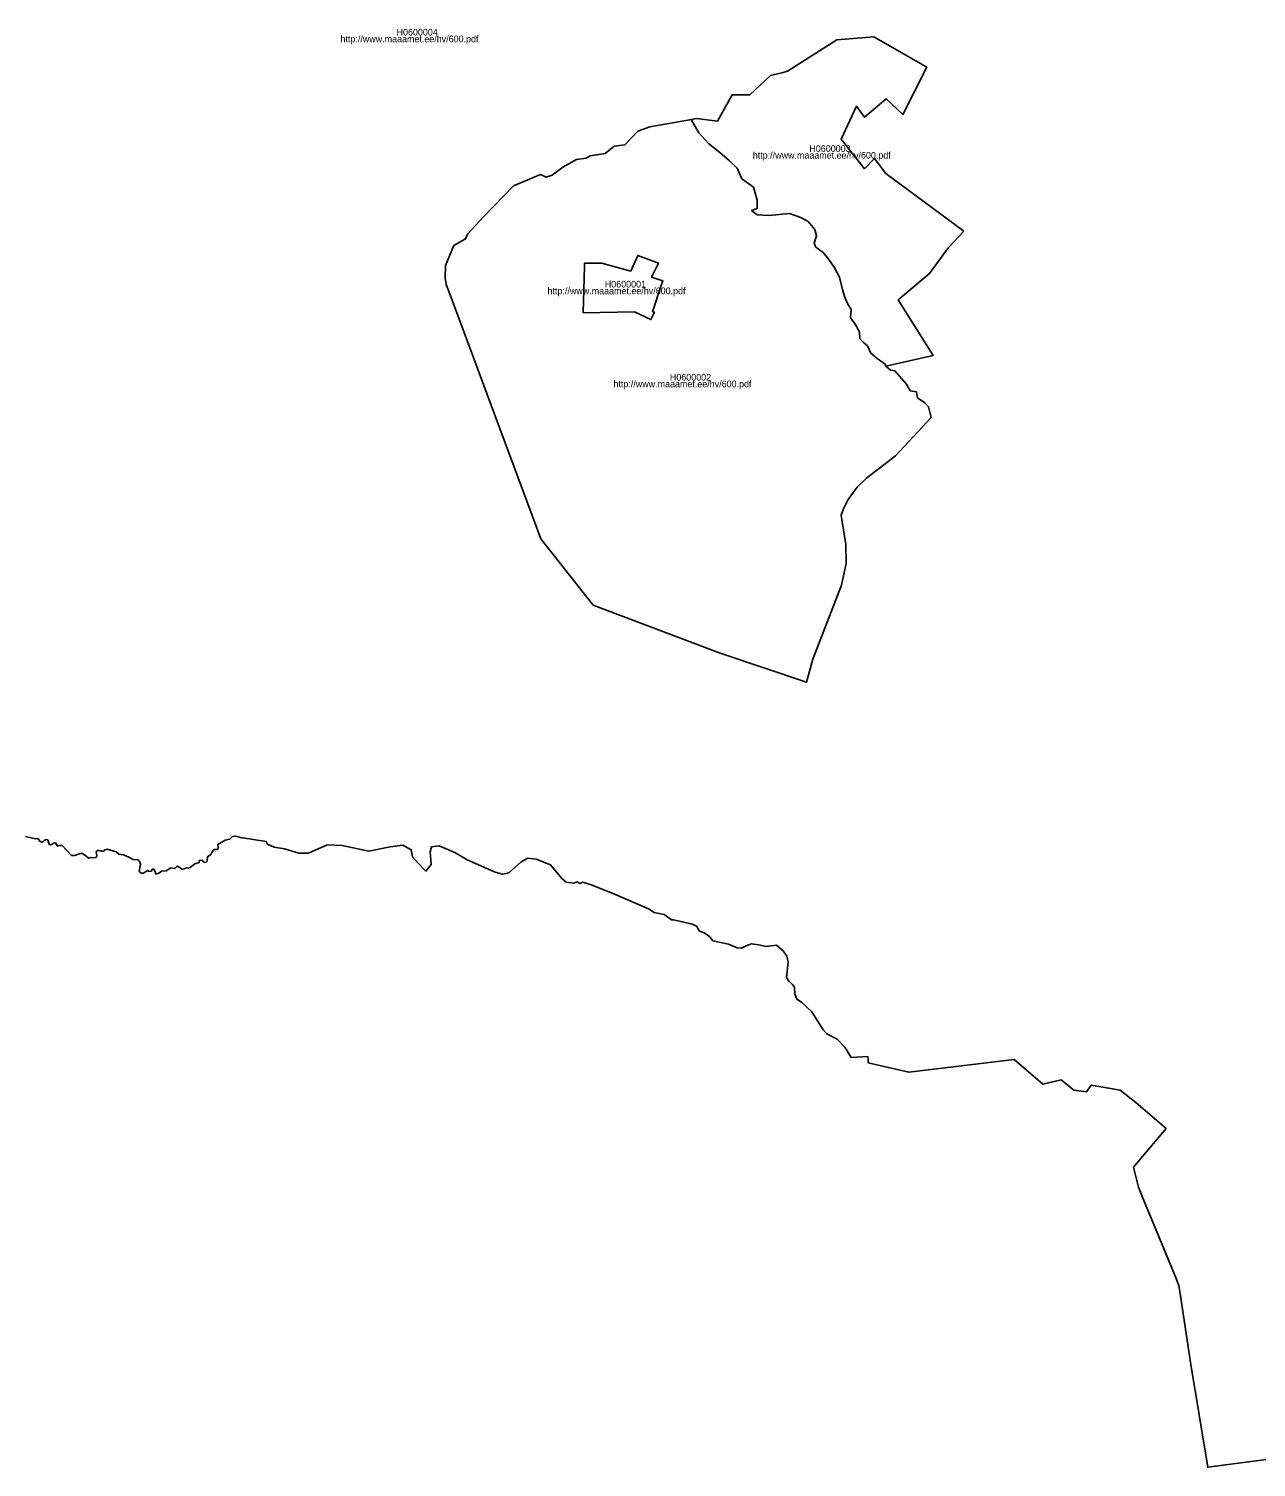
# Model space of a CAD drawing. Extents: x 369010 to 739155, y 6377141 to 6634081.
# Drawn here: x 588944 to 593540, y 6437007 to 6442393 of the extents above; entities that cross this region are included whole.
import ezdxf

# ---------------------------------------------------------------- set-up
doc = ezdxf.new("R2010")
doc.units = 0
for name, color, linetype in [('H_LINK', 7, 'Continuous'), ('H_PIIR', 7, 'Continuous'), ('H_TUNNUS', 7, 'Continuous')]:
    doc.layers.add(name, color=color, linetype=linetype)

msp = doc.modelspace()

# ---------------------------------------------------------------- linework, layer by layer
at = {"layer": 'H_PIIR'}
for points in [[(592108.2801, 6442363), (591969.52, 6442351.0799), (591785.26, 6442234.28), (591768.3599, 6442229.9701), (591721.22, 6442217.95), (591643.37, 6442146.3701), (591577.4501, 6442145.7401), (591522.83, 6442047.16), (591444.0299, 6442056.58), (591424.6895, 6442053.1702), (591269.5, 6442025.81), (591224.9201, 6442010.1099), (591175.3201, 6441958.62), (591135.4601, 6441953.6001), (591102.18, 6441926.6), (591046.3, 6441917.1799), (591031.24, 6441909.0199), (590994.2001, 6441903.3599), (590943.9701, 6441875.1101), (590903.79, 6441844.97), (590881.0701, 6441837.78), (590860.1499, 6441847.4801), (590788.6099, 6441817.26), (590759.07, 6441804.7801), (590647.3199, 6441689.8699), (590586.1099, 6441624.5699), (590579.1999, 6441606.36), (590535.25, 6441581.8699), (590504.49, 6441506.5201), (590503.23, 6441459.42), (590506.9999, 6441435.56), (590521.5299, 6441396.53), (590861.72, 6440483), (591057.6101, 6440234.97), (591533.18, 6440055.3801), (591855.5701, 6439946.1299), (591879.43, 6440033.4101), (591987.1001, 6440309.6899), (592004.06, 6440391.32), (592003.43, 6440462.28), (591985.54, 6440572.1599), (591993.7, 6440592.89), (592003.1099, 6440612.98), (592011.9001, 6440631.1901), (592045.8099, 6440676.4), (592080.34, 6440710.94), (592189.5799, 6440793.8199), (592322.9901, 6440938.24), (592312.9499, 6440977.7999), (592299.1399, 6440992.8699), (592271.5099, 6441011.71), (592267.12, 6441034.3199), (592244.5101, 6441038.08), (592230.0701, 6441062.57), (592186.7501, 6441112.8099), (592169.8, 6441114.6901), (592153.1599, 6441130.39), (592329.58, 6441169.9499), (592199.62, 6441377.7901), (592316.71, 6441477.0001), (592387.0301, 6441574.33), (592444.79, 6441635.24), (592153.1599, 6441850.61), (592110.4699, 6441907.13), (592073.43, 6441868.8201), (591986.16, 6441979.34), (592042.67, 6442103.6701), (592072.4901, 6442062.22), (592154.11, 6442131.2901), (592216.89, 6442072.27), (592306.0399, 6442248.72)], [(592108.2801, 6442363), (592306.0399, 6442248.72), (592216.89, 6442072.27), (592154.11, 6442131.2901), (592072.4901, 6442062.22), (592042.67, 6442103.6701), (591986.16, 6441979.34), (592073.43, 6441868.8201), (592110.4699, 6441907.13), (592153.1599, 6441850.61), (592444.79, 6441635.24), (592387.0301, 6441574.33), (592316.71, 6441477.0001), (592199.62, 6441377.7901), (592329.58, 6441169.9499), (592153.1599, 6441130.39), (592150.05, 6441137.56), (592120.08, 6441159.1001), (592097.03, 6441179.09), (592083.9599, 6441205.7899), (592068.59, 6441219.6299), (592055.53, 6441232.7), (592053.9899, 6441258.08), (592038.62, 6441286.5299), (592020.95, 6441311), (592022.49, 6441342.5199), (592009.42, 6441364.82), (591998.6701, 6441390.9699), (591990.98, 6441417.11), (591979.45, 6441462.4799), (591959.4701, 6441500.5199), (591939.5, 6441528.9501), (591918.75, 6441555.08), (591891.08, 6441575.83), (591884.17, 6441590.43), (591893.39, 6441618.09), (591886.47, 6441641.15), (591861.8801, 6441671.12), (591834.2201, 6441686.5001), (591792.7201, 6441702.0601), (591714.92, 6441694.28), (591670.8299, 6441696.8701), (591650.0799, 6441712.4301), (591670.8299, 6441720.22), (591670.8299, 6441751.34), (591657.86, 6441800.6099), (591613.7701, 6441831.7399), (591595.62, 6441870.64), (591567.0901, 6441899.17), (591530.7801, 6441930.29), (591489.28, 6441964.0101), (591452.97, 6442002.91), (591425.7701, 6442051.25), (591424.6895, 6442053.1702), (591444.0299, 6442056.58), (591522.83, 6442047.16), (591577.4501, 6442145.7401), (591643.37, 6442146.3701), (591721.22, 6442217.95), (591768.3599, 6442229.9701), (591785.26, 6442234.28), (591969.52, 6442351.0799)], [(591424.6895, 6442053.1702), (591425.7701, 6442051.25), (591452.97, 6442002.91), (591489.28, 6441964.0101), (591530.7801, 6441930.29), (591567.0901, 6441899.17), (591595.62, 6441870.64), (591613.7701, 6441831.7399), (591657.86, 6441800.6099), (591670.8299, 6441751.34), (591670.8299, 6441720.22), (591650.0799, 6441712.4301), (591670.8299, 6441696.8701), (591714.92, 6441694.28), (591792.7201, 6441702.0601), (591834.2201, 6441686.5001), (591861.8801, 6441671.12), (591886.47, 6441641.15), (591893.39, 6441618.09), (591884.17, 6441590.43), (591891.08, 6441575.83), (591918.75, 6441555.08), (591939.5, 6441528.9501), (591959.4701, 6441500.5199), (591979.45, 6441462.4799), (591990.98, 6441417.11), (591998.6701, 6441390.9699), (592009.42, 6441364.82), (592022.49, 6441342.5199), (592020.95, 6441311), (592038.62, 6441286.5299), (592053.9899, 6441258.08), (592055.53, 6441232.7), (592068.59, 6441219.6299), (592083.9599, 6441205.7899), (592097.03, 6441179.09), (592120.08, 6441159.1001), (592150.05, 6441137.56), (592153.1599, 6441130.39), (592155.1686, 6441128.4949), (592169.8, 6441114.6901), (592186.7501, 6441112.8099), (592230.0701, 6441062.57), (592244.5101, 6441038.08), (592267.12, 6441034.3199), (592271.5099, 6441011.71), (592299.1399, 6440992.8699), (592312.9499, 6440977.7999), (592322.9901, 6440938.24), (592189.5799, 6440793.8199), (592080.34, 6440710.94), (592045.8099, 6440676.4), (592011.9001, 6440631.1901), (592003.1099, 6440612.98), (591993.7, 6440592.89), (591985.54, 6440572.1599), (592003.43, 6440462.28), (592004.06, 6440391.32), (591987.1001, 6440309.6899), (591879.43, 6440033.4101), (591855.5701, 6439946.1299), (591533.18, 6440055.3801), (591057.6101, 6440234.97), (590861.72, 6440483), (590521.5299, 6441396.53), (590506.9999, 6441435.56), (590503.23, 6441459.42), (590504.49, 6441506.5201), (590535.25, 6441581.8699), (590579.1999, 6441606.36), (590586.1099, 6441624.5699), (590647.3199, 6441689.8699), (590759.07, 6441804.7801), (590788.6099, 6441817.26), (590860.1499, 6441847.4801), (590881.0701, 6441837.78), (590903.79, 6441844.97), (590943.9701, 6441875.1101), (590994.2001, 6441903.3599), (591031.24, 6441909.0199), (591046.3, 6441917.1799), (591102.18, 6441926.6), (591135.4601, 6441953.6001), (591175.3201, 6441958.62), (591224.9201, 6442010.1099), (591269.5, 6442025.81)], [(591224.03, 6441544.5701), (591301.84, 6441515.1701), (591275.9, 6441463.29), (591317.41, 6441449.45), (591312.22, 6441432.16), (591279.36, 6441333.59), (591286.28, 6441331.86), (591272.45, 6441304.19), (591211.92, 6441333.59), (591019.9699, 6441330.13), (591025.1599, 6441503.0601), (591025.1599, 6441515.1701), (591089.14, 6441515.1701), (591198.09, 6441485.77)], [(591089.14, 6441515.1701), (591025.1599, 6441515.1701), (591025.1599, 6441503.0601), (591019.9699, 6441330.13), (591211.92, 6441333.59), (591272.45, 6441304.19), (591286.28, 6441331.86), (591279.36, 6441333.59), (591312.22, 6441432.16), (591317.41, 6441449.45), (591275.9, 6441463.29), (591301.84, 6441515.1701), (591224.03, 6441544.5701), (591198.09, 6441485.77)]]:
    msp.add_lwpolyline(points, close=True, dxfattribs=at)
for points in [[(588931.56, 6439368.48), (588968.69, 6439360.0501), (588976.72, 6439361.06), (588981.5901, 6439357.51), (588984.89, 6439351), (588991.3901, 6439347.3399), (588995.25, 6439347.8499), (589001.2401, 6439353.54), (589009.06, 6439357.3), (589015.1601, 6439355.9799), (589019.7301, 6439340.13), (589024.46, 6439337.4199), (589032.2799, 6439340.67), (589037.5601, 6439345.6501), (589043.45, 6439344.63), (589051.3299, 6439332.74), (589057.6299, 6439334.6701), (589068.7601, 6439334.6701), (589104.3599, 6439298.3001), (589116.34, 6439297.7901), (589135.84, 6439304.8), (589145.14, 6439305.01), (589157.5299, 6439296.0601), (589167.4801, 6439287.4301), (589174.59, 6439290.37), (589186.3199, 6439288.9499), (589195.97, 6439290.2701), (589198.6101, 6439296.17), (589196.58, 6439312.2201), (589203.6799, 6439317.51), (589214.86, 6439313.44), (589224.77, 6439314.05), (589228.82, 6439319.34), (589237.96, 6439321.3699), (589271.48, 6439311.41), (589281.6901, 6439302.18), (589298.21, 6439299.84), (589318.83, 6439291.63), (589334.88, 6439282.48), (589352.35, 6439281.4899), (589358.8, 6439276.22), (589362.54, 6439265.72), (589356.7101, 6439239.65), (589363.74, 6439231.3399), (589373.3601, 6439231.2), (589388.65, 6439242.04), (589395.1799, 6439238.3801), (589403.3499, 6439239.24), (589406.2801, 6439246.56), (589411.83, 6439246.51), (589416.39, 6439240.32), (589419.5401, 6439228.4499), (589430.28, 6439231.52), (589440.7399, 6439238.9501), (589457.83, 6439240.1201), (589476.33, 6439251.0101), (589488.2701, 6439249.65), (589492.8801, 6439251.5099), (589497.8, 6439256.47), (589501.23, 6439257.47), (589509.25, 6439253.04), (589517.41, 6439246.3099), (589525.9, 6439248.34), (589536.27, 6439252.1399), (589542.06, 6439250.9199), (589548.6, 6439252.45), (589565.21, 6439266.16), (589581.6199, 6439271.45), (589582.38, 6439279.07), (589593.6499, 6439280.29), (589599.9, 6439272.8199), (589606.9, 6439271.7499), (589612.39, 6439276.4801), (589613.4501, 6439293.0899), (589625.15, 6439300.98), (589630.33, 6439311.95), (589637.6401, 6439320.03), (589650.08, 6439320.03), (589652.5199, 6439325.3599), (589652.21, 6439339.54), (589679.46, 6439355.5401), (589696.21, 6439359.3499), (589706.11, 6439368.6499), (589718.75, 6439369.72), (589736.04, 6439365.6), (589833.2801, 6439350.05), (589837.6999, 6439340), (589862.49, 6439328.56), (589900.8101, 6439322.16), (589954.4201, 6439306.3099), (589990.87, 6439306.4701), (590060.6101, 6439337.73), (590117.49, 6439334.6501), (590216.64, 6439313.8801), (590297.35, 6439330.8), (590344.23, 6439336.19), (590375.75, 6439319.27), (590381.13, 6439292.35), (590398.81, 6439271.58), (590431.09, 6439239.28), (590450.3, 6439263.89), (590446.7, 6439311.42), (590452.17, 6439330.79), (590481.0499, 6439334.21), (590538.8399, 6439309.14), (590585.3, 6439281.1101), (590690.0301, 6439235.21), (590718.1899, 6439227.46), (590741.65, 6439232.4699), (590786.8799, 6439274.1701), (590812.3901, 6439287.62), (590843.81, 6439284.2), (590897.9, 6439262.4899), (590940.26, 6439211.93), (590956.2, 6439197.3601), (590983.45, 6439194.24), (590997.79, 6439199.36), (591007.01, 6439192.53), (591018.62, 6439197.3099), (591049.9599, 6439188.43), (591134.9901, 6439153.91), (591264.0299, 6439098.26), (591285.21, 6439083.92), (591323.12, 6439076.51), (591350.5599, 6439056.5199), (591358.2401, 6439057.0399), (591428.41, 6439041.15), (591444.29, 6439033.4599), (591455.0499, 6439013.98), (591472.9799, 6439008.35), (591492.95, 6438993.99), (591505.2399, 6438978.1001), (591564.1501, 6438965.2899), (591596.08, 6438951.4499), (591611.9599, 6438950.4301), (591629.8899, 6438959.6501), (591650.37, 6438966.83), (591677.01, 6438963.24), (591703.64, 6438957.09), (591743.0801, 6438962.22), (591768.18, 6438941.2001), (591782.52, 6438921.21), (591787.64, 6438897.9401), (591781.5, 6438840.53), (591789.6899, 6438827.21), (591804.04, 6438814.39), (591811.2101, 6438804.65), (591812.7399, 6438780.0499), (591819.6899, 6438759.75), (591837.1001, 6438748.9899), (591875.52, 6438712.0799), (591918.03, 6438644.4599), (591931.86, 6438630.1199), (591970.79, 6438609.63), (591998.96, 6438579.9199), (592023.03, 6438542.01), (592084.88, 6438545.54), (592086.3901, 6438535.5301), (592086.45, 6438521.8001), (592238.5999, 6438486.23), (592633.09, 6438533.7899), (592741.2101, 6438441.13), (592809.1799, 6438457.26), (592856.41, 6438419.24), (592904.79, 6438413.48), (592922.07, 6438437.67), (593030.3601, 6438419.24), (593089.1101, 6438373.16), (593202.2001, 6438275.45), (593080.11, 6438131.37), (593098.54, 6438056.46), (593121.58, 6437999.9799), (593163.0401, 6437901.4199), (593240.2099, 6437713.55), (593249.4299, 6437687.04), (593254.0299, 6437665.24), (593294.35, 6437392.26), (593357.9901, 6437007.37), (593596.43, 6437038.46)], [(593596.43, 6437038.46), (593357.9901, 6437007.37), (593294.35, 6437392.26), (593254.0299, 6437665.24), (593249.4299, 6437687.04), (593240.2099, 6437713.55), (593163.0401, 6437901.4199), (593121.58, 6437999.9799), (593098.54, 6438056.46), (593080.11, 6438131.37), (593202.2001, 6438275.45), (593089.1101, 6438373.16), (593030.3601, 6438419.24), (592922.07, 6438437.67), (592904.79, 6438413.48), (592856.41, 6438419.24), (592809.1799, 6438457.26), (592741.2101, 6438441.13), (592633.09, 6438533.7899), (592238.5999, 6438486.23), (592086.45, 6438521.8001), (592086.3901, 6438535.5301), (592084.88, 6438545.54), (592023.03, 6438542.01), (591998.96, 6438579.9199), (591970.79, 6438609.63), (591931.86, 6438630.1199), (591918.03, 6438644.4599), (591875.52, 6438712.0799), (591837.1001, 6438748.9899), (591819.6899, 6438759.75), (591812.7399, 6438780.0499), (591811.2101, 6438804.65), (591804.04, 6438814.39), (591789.6899, 6438827.21), (591781.5, 6438840.53), (591787.64, 6438897.9401), (591782.52, 6438921.21), (591768.18, 6438941.2001), (591743.0801, 6438962.22), (591703.64, 6438957.09), (591677.01, 6438963.24), (591650.37, 6438966.83), (591629.8899, 6438959.6501), (591611.9599, 6438950.4301), (591596.08, 6438951.4499), (591564.1501, 6438965.2899), (591505.2399, 6438978.1001), (591492.95, 6438993.99), (591472.9799, 6439008.35), (591455.0499, 6439013.98), (591444.29, 6439033.4599), (591428.41, 6439041.15), (591358.2401, 6439057.0399), (591350.5599, 6439056.5199), (591323.12, 6439076.51), (591285.21, 6439083.92), (591264.0299, 6439098.26), (591134.9901, 6439153.91), (591049.9599, 6439188.43), (591018.62, 6439197.3099), (591007.01, 6439192.53), (590997.79, 6439199.36), (590983.45, 6439194.24), (590956.2, 6439197.3601), (590940.26, 6439211.93), (590897.9, 6439262.4899), (590843.81, 6439284.2), (590812.3901, 6439287.62), (590786.8799, 6439274.1701), (590741.65, 6439232.4699), (590718.1899, 6439227.46), (590690.0301, 6439235.21), (590585.3, 6439281.1101), (590538.8399, 6439309.14), (590481.0499, 6439334.21), (590452.17, 6439330.79), (590446.7, 6439311.42), (590450.3, 6439263.89), (590431.09, 6439239.28), (590398.81, 6439271.58), (590381.13, 6439292.35), (590375.75, 6439319.27), (590344.23, 6439336.19), (590297.35, 6439330.8), (590216.64, 6439313.8801), (590117.49, 6439334.6501), (590060.6101, 6439337.73), (589990.87, 6439306.4701), (589954.4201, 6439306.3099), (589900.8101, 6439322.16), (589862.49, 6439328.56), (589837.6999, 6439340), (589833.2801, 6439350.05), (589736.04, 6439365.6), (589718.75, 6439369.72), (589706.11, 6439368.6499), (589696.21, 6439359.3499), (589679.46, 6439355.5401), (589652.21, 6439339.54), (589652.5199, 6439325.3599), (589650.08, 6439320.03), (589637.6401, 6439320.03), (589630.33, 6439311.95), (589625.15, 6439300.98), (589613.4501, 6439293.0899), (589612.39, 6439276.4801), (589606.9, 6439271.7499), (589599.9, 6439272.8199), (589593.6499, 6439280.29), (589582.38, 6439279.07), (589581.6199, 6439271.45), (589565.21, 6439266.16), (589548.6, 6439252.45), (589542.06, 6439250.9199), (589536.27, 6439252.1399), (589525.9, 6439248.34), (589517.41, 6439246.3099), (589509.25, 6439253.04), (589501.23, 6439257.47), (589497.8, 6439256.47), (589492.8801, 6439251.5099), (589488.2701, 6439249.65), (589476.33, 6439251.0101), (589457.83, 6439240.1201), (589440.7399, 6439238.9501), (589430.28, 6439231.52), (589419.5401, 6439228.4499), (589416.39, 6439240.32), (589411.83, 6439246.51), (589406.2801, 6439246.56), (589403.3499, 6439239.24), (589395.1799, 6439238.3801), (589388.65, 6439242.04), (589373.3601, 6439231.2), (589363.74, 6439231.3399), (589356.7101, 6439239.65), (589362.54, 6439265.72), (589358.8, 6439276.22), (589352.35, 6439281.4899), (589334.88, 6439282.48), (589318.83, 6439291.63), (589298.21, 6439299.84), (589281.6901, 6439302.18), (589271.48, 6439311.41), (589237.96, 6439321.3699), (589228.82, 6439319.34), (589224.77, 6439314.05), (589214.86, 6439313.44), (589203.6799, 6439317.51), (589196.58, 6439312.2201), (589198.6101, 6439296.17), (589195.97, 6439290.2701), (589186.3199, 6439288.9499), (589174.59, 6439290.37), (589167.4801, 6439287.4301), (589157.5299, 6439296.0601), (589145.14, 6439305.01), (589135.84, 6439304.8), (589116.34, 6439297.7901), (589104.3599, 6439298.3001), (589068.7601, 6439334.6701), (589057.6299, 6439334.6701), (589051.3299, 6439332.74), (589043.45, 6439344.63), (589037.5601, 6439345.6501), (589032.2799, 6439340.67), (589024.46, 6439337.4199), (589019.7301, 6439340.13), (589015.1601, 6439355.9799), (589009.06, 6439357.3), (589001.2401, 6439353.54), (588995.25, 6439347.8499), (588991.3901, 6439347.3399), (588984.89, 6439351), (588981.5901, 6439357.51), (588976.72, 6439361.06), (588968.69, 6439360.0501), (588931.56, 6439368.48)]]:
    msp.add_lwpolyline(points, dxfattribs=at)

# ---------------------------------------------------------------- texts
at = {"layer": 'H_LINK'}
for p in [(590111.0707, 6442342.7265), (591654.7654, 6441906.9889), (590886.2381, 6441399.38)]:
    msp.add_text('http://www.maaamet.ee/hv/600.pdf', height=25, dxfattribs=at).set_placement(p)
msp.add_text('http://www.maaamet.ee/hv/600.pdf', height=25, rotation=0, dxfattribs=at).set_placement((591133.1357, 6441050.9255))
at = {"layer": 'H_TUNNUS'}
for s, p in [('H0600004', (590321.0499, 6442367.7265)), ('H0600003', (591866.6199, 6441931.9889)), ('H0600001', (591100.5921, 6441424.38))]:
    msp.add_text(s, height=25, dxfattribs=at).set_placement(p)
msp.add_text('H0600002', height=25, rotation=0, dxfattribs=at).set_placement((591344.3646, 6441075.9255))

doc.saveas('drawing.dxf')
